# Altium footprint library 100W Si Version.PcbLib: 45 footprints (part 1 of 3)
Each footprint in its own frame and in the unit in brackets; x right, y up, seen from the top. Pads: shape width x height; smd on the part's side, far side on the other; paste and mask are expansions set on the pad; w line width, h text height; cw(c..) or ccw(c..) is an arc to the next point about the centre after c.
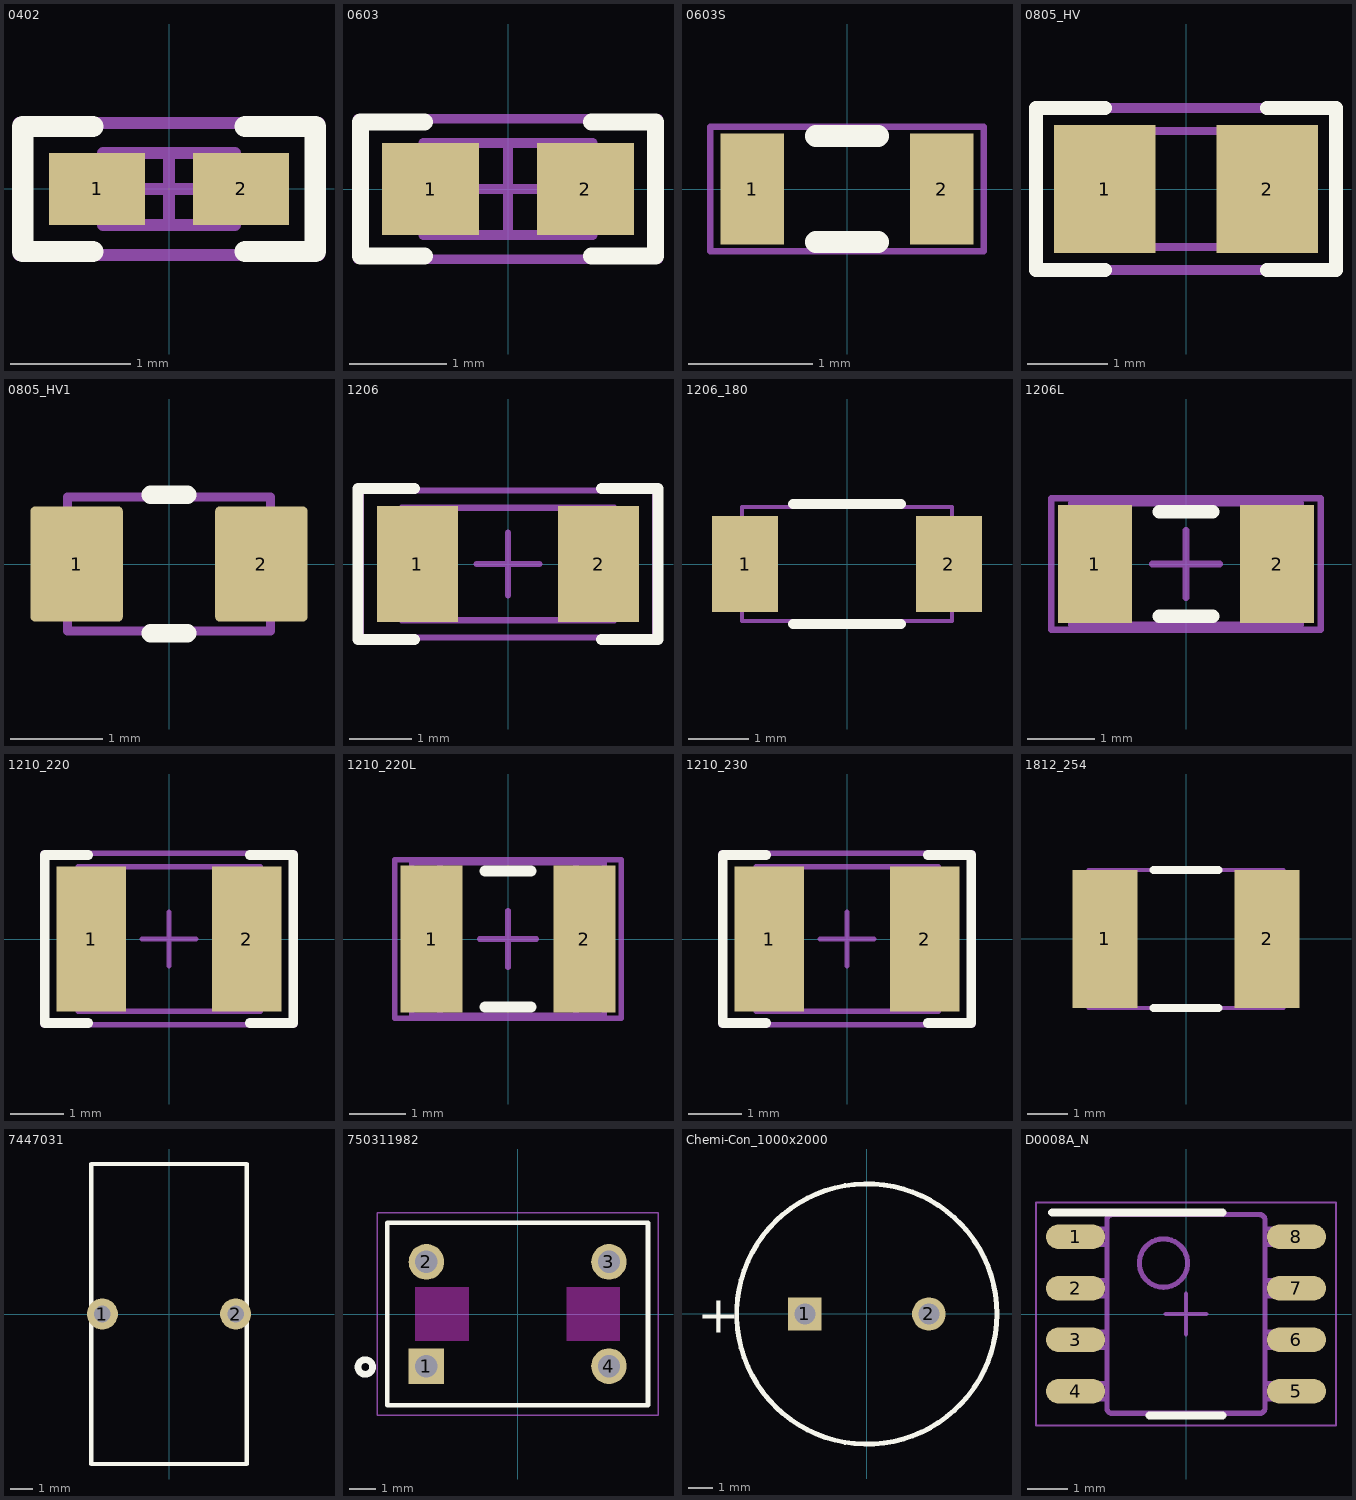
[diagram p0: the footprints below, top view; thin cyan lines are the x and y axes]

## 0402 [mm] "0402 from SM-752 data"
height 0.6
pads (2):
  rect 0.8x0.6 smd: 1(-0.6,0) 2(0.6,0)
Top Overlay:
  lines w0.178: -0.635,-0.521 -1.219,-0.521 -1.219,0.521 -0.635,0.521 ; 0.635,-0.521 1.219,-0.521 1.219,0.521 0.635,0.521
Mechanical 5:
  lines w0.1: -1.25,-0.55 1.25,-0.55 1.25,0.55 -1.25,0.55 -1.25,-0.55
  text ".Designator" at -1.117,-0.305 h0.76
Mechanical 13:
  lines w0.1: -0.35,-0.3 -0.35,0.3 ; 0.35,-0.3 0.35,0.3 ; -0.55,-0.3 -0.55,0.3 0.55,0.3 0.55,-0.3 -0.55,-0.3
Mechanical 15:
  lines w0.1: -0.3,0 0.3,0 ; 0,-0.3 0,0.3 ; -1.25,-0.55 -1.25,0.55 1.25,0.55 1.25,-0.55 -1.25,-0.55
3D body: height 0.6, standoff 0, extent -0.549,-0.299 -0.351,0.299
3D body: height 0.6, standoff 0, extent -0.349,-0.299 0.349,0.299
3D body: height 0.6, standoff 0, extent 0.351,-0.299 0.549,0.299

## 0603 [mm] "0603 from SM-752 data"
height 1
pads (2):
  rect 1x0.95 smd: 1(-0.8,0) 2(0.8,0)
Top Overlay:
  lines w0.178: -0.864,-0.691 -1.524,-0.691 -1.524,0.693 -0.864,0.693 ; 0.864,-0.691 1.524,-0.691 1.524,0.693 0.864,0.693
Mechanical 5:
  lines w0.1: -1.55,-0.725 1.55,-0.725 1.55,0.725 -1.55,0.725 -1.55,-0.725
  text ".Designator" at -1.397,-0.381 h0.76
Mechanical 13:
  lines w0.1: -0.55,-0.475 -0.55,0.475 ; 0.55,-0.475 0.55,0.475 ; -0.875,-0.475 -0.875,0.475 0.875,0.475 0.875,-0.475 -0.875,-0.475
Mechanical 15:
  lines w0.1: -0.475,0 0.475,0 ; 0,-0.475 0,0.475 ; -1.55,-0.725 -1.55,0.725 1.55,0.725 1.55,-0.725 -1.55,-0.725
3D body: height 1, standoff 0, extent 0.551,-0.474 0.874,0.474
3D body: height 1, standoff 0, extent -0.549,-0.474 0.549,0.474
3D body: height 1, standoff 0, extent -0.874,-0.474 -0.551,0.474

## 0603S [mil]
height 39.37
pads (2):
  rect 20x35 smd: 1(-30,0) 2(30,0)
Top Overlay:
  lines w7: -9.84,-16.73 9.84,-16.73 ; -9.84,16.73 9.84,16.73
Mechanical 5:
  lines w1.97: -43.31,-19.68 43.31,-19.68 43.31,19.68 -43.31,19.68 -43.31,-19.68
  text ".Designator" at -32.48,-8.86 h30
3D body: height 39.37, standoff 0, extent -34.43,-18.68 -21.67,18.68
3D body: height 39.37, standoff 0, extent -21.63,-18.68 21.63,18.68
3D body: height 39.37, standoff 0, extent 21.67,-18.68 34.43,18.68

## 0805_HV [mil] "0805 with 30mil clearance between pads"
height 57.09
pads (2):
  rect 50x63 smd: 1(-40,0) 2(40,0)
Top Overlay:
  lines w7: -40,-40 -74,-40 -74,0 -74,40 -40,40 ; 40,-40 74,-40 74,0 74,40 40,40
Mechanical 5:
  lines w5: -74,-40 -74,40 74,40 74,-40 -74,-40
  text ".Designator" at -64,-17 h35
Mechanical 13:
  lines w3.94: -25.59,-28.54 -25.59,28.54 ; 25.59,-28.54 25.59,28.54 ; -43.31,-28.54 -43.31,28.54 43.31,28.54 43.31,-28.54 -43.31,-28.54
3D body: height 57.09, standoff 0, extent 25.61,-28.52 43.29,28.52
3D body: height 57.09, standoff 0, extent -25.57,-28.52 25.57,28.52
3D body: height 57.09, standoff 0, extent -43.29,-28.52 -25.61,28.52

## 0805_HV1 [mm] "Custom footprint based on analyzing multiple manufacturer recommendations"
height 1.45
pads (2):
  rrect10% 1x1.25 smd: 1(-1,0) 2(1,0)
Top Overlay:
  lines w0.2: -0.2,-0.75 0.2,-0.75 ; -0.2,0.75 0.2,0.75
Mechanical 5:
  lines w0.1: -1.1,-0.725 -1.1,0.725 1.1,0.725 1.1,-0.725 -1.1,-0.725
  text ".Designator" at -0.925,-0.25 h0.51
3D body "0805_CapMax.stp": height 1.45, standoff 0, extent -1.1,-0.725 1.1,0.725

## 1206 [mm] "1206 from SM-752 data"
height 1.35
pads (2):
  rect 1.3x1.85 smd: 1(-1.45,0) 2(1.45,0)
Top Overlay:
  lines w0.178: -1.5,-1.21 -2.4,-1.21 -2.4,1.21 -1.5,1.21 ; 1.5,-1.21 2.4,-1.21 2.4,1.21 1.5,1.21
Mechanical 5:
  lines w0.1: -1.7,-0.9 1.7,-0.9 1.7,0.9 -1.7,0.9 -1.7,-0.9
  text ".Designator" at -1.475,-0.4 h0.81
Mechanical 13:
  lines w0.1: -1.2,-0.9 -1.2,0.9 ; 1.2,-0.9 1.2,0.9 ; -1.7,-0.9 1.7,-0.9 1.7,0.9 -1.7,0.9 -1.7,-0.9
Mechanical 15:
  lines w0.1: -0.5,0 0.5,0 ; 0,-0.5 0,0.5 ; -2.35,-1.175 2.35,-1.175 2.35,1.175 -2.35,1.175 -2.35,-1.175
3D body: height 1.35, standoff 0, extent -1.699,-0.899 -1.201,0.899
3D body: height 1.35, standoff 0, extent -1.199,-0.899 1.199,0.899
3D body: height 1.35, standoff 0, extent 1.201,-0.899 1.699,0.899

## 1206_180 [mm] "1206_180"
height 1.8
pads (2):
  rect 1.1x1.6 smd: 1(-1.7,0) 2(1.7,0)
Top Overlay:
  lines w0.17: -0.9,-1 0.9,-1 ; -0.9,1 0.9,1
Mechanical 5:
  lines w0.07: -1.75,-0.95 1.75,-0.95 1.75,0.95 -1.75,0.95 -1.75,-0.95
3D body: height 1.8, standoff 0, extent -1.749,-0.949 -1.301,0.949
3D body: height 1.8, standoff 0, extent -1.299,-0.949 1.299,0.949
3D body: height 1.8, standoff 0, extent 1.301,-0.949 1.749,0.949

## 1206L [mm] "1206 from SM-752 data"
height 1.35
pads (2):
  rect 1.1x1.75 smd: 1(-1.35,0) 2(1.35,0)
Top Overlay:
  lines w0.2: -0.4,-0.775 0.4,-0.775 ; -0.4,0.775 0.4,0.775
Mechanical 5:
  lines w0.1: -1.7,-0.9 1.7,-0.9 1.7,0.9 -1.7,0.9 -1.7,-0.9
  text ".Designator" at -1.475,-0.4 h0.81
Mechanical 13:
  lines w0.1: -1.2,-0.9 -1.2,0.9 ; 1.2,-0.9 1.2,0.9 ; -1.7,-0.9 -1.7,0.9 1.7,0.9 1.7,-0.9 -1.7,-0.9
Mechanical 15:
  lines w0.1: -0.5,0 0.5,0 ; 0,-0.5 0,0.5 ; -2,-0.975 2,-0.975 2,0.975 -2,0.975 -2,-0.975
3D body: height 1.35, standoff 0, extent 1.201,-0.899 1.699,0.899
3D body: height 1.35, standoff 0, extent -1.199,-0.899 1.199,0.899
3D body: height 1.35, standoff 0, extent -1.699,-0.899 -1.201,0.899

## 1210_220 [mm] "1210"
height 2.2
pads (2):
  rect 1.3x2.7 smd: 1(-1.45,0) 2(1.45,0)
Top Overlay:
  lines w0.178: -1.511,-1.568 -2.316,-1.568 -2.316,1.568 -1.511,1.568 ; 1.511,-1.568 2.316,-1.568 2.316,1.568 1.511,1.568
Mechanical 5:
  lines w0.1: -1.7,-1.35 -1.7,1.35 1.7,1.35 1.7,-1.35 -1.7,-1.35
  text ".Designator" at -1.4,-0.375 h0.76
Mechanical 13:
  lines w0.1: -1.2,-1.35 -1.2,1.35 ; 1.2,-1.35 1.2,1.35 ; -1.7,-1.35 1.7,-1.35 1.7,1.35 -1.7,1.35 -1.7,-1.35
Mechanical 15:
  lines w0.1: -0.5,0 0.5,0 ; 0,-0.5 0,0.5 ; -2.35,-1.6 2.35,-1.6 2.35,1.6 -2.35,1.6 -2.35,-1.6
3D body: height 2.2, standoff 0, extent 1.201,-1.349 1.699,1.349
3D body: height 2.2, standoff 0, extent -1.199,-1.349 1.199,1.349
3D body: height 2.2, standoff 0, extent -1.699,-1.349 -1.201,1.349

## 1210_220L [mm] "1210"
height 2.2
pads (2):
  rect 1.1x2.6 smd: 1(-1.35,0) 2(1.35,0)
Top Overlay:
  lines w0.2: -0.4,-1.2 0.4,-1.2 ; -0.4,1.2 0.4,1.2
Mechanical 5:
  lines w0.1: -1.7,-1.35 1.7,-1.35 1.7,1.35 -1.7,1.35 -1.7,-1.35
  text ".Designator" at -1.4,-0.375 h0.76
Mechanical 13:
  lines w0.1: -1.2,-1.35 -1.2,1.35 ; 1.2,-1.35 1.2,1.35 ; -1.7,-1.35 1.7,-1.35 1.7,1.35 -1.7,1.35 -1.7,-1.35
Mechanical 15:
  lines w0.1: -0.5,0 0.5,0 ; 0,-0.5 0,0.5 ; -2,-1.4 -2,1.4 2,1.4 2,-1.4 -2,-1.4
3D body: height 2.2, standoff 0, extent 1.201,-1.349 1.699,1.349
3D body: height 2.2, standoff 0, extent -1.199,-1.349 1.199,1.349
3D body: height 2.2, standoff 0, extent -1.699,-1.349 -1.201,1.349

## 1210_230 [mm] "1210"
height 2.3
pads (2):
  rect 1.3x2.7 smd: 1(-1.45,0) 2(1.45,0)
Top Overlay:
  lines w0.178: -1.511,-1.568 -2.316,-1.568 -2.316,1.568 -1.511,1.568 ; 1.511,-1.568 2.316,-1.568 2.316,1.568 1.511,1.568
Mechanical 5:
  lines w0.1: -1.7,-1.35 1.7,-1.35 1.7,1.35 -1.7,1.35 -1.7,-1.35
  text ".Designator" at -1.4,-0.375 h0.76
Mechanical 13:
  lines w0.1: -1.2,-1.35 -1.2,1.35 ; 1.2,-1.35 1.2,1.35 ; -1.7,-1.35 -1.7,1.35 1.7,1.35 1.7,-1.35 -1.7,-1.35
Mechanical 15:
  lines w0.1: -0.5,0 0.5,0 ; 0,-0.5 0,0.5 ; -2.35,-1.6 -2.35,1.6 2.35,1.6 2.35,-1.6 -2.35,-1.6
3D body: height 2.3, standoff 0, extent -1.699,-1.349 -1.201,1.349
3D body: height 2.3, standoff 0, extent -1.199,-1.349 1.199,1.349
3D body: height 2.3, standoff 0, extent 1.201,-1.349 1.699,1.349

## 1812_254 [mm] "SMD, 2-Leads, Body 4.8x3.4mm"
height 2.54
pads (2):
  rect 1.6x3.4 smd: 1(-2,0) 2(2,0)
Top Overlay:
  lines w0.2: -0.8,-1.7 0.8,-1.7 ; -0.8,1.7 0.8,1.7
Mechanical 5:
  lines w0.1: -1.9,-1.7 -1.9,1.7 ; 1.9,-1.7 1.9,1.7 ; -2.4,-1.7 2.4,-1.7 2.4,1.7 -2.4,1.7 -2.4,-1.7
  text ".Designator" at -1.875,-0.5 h1.02
3D body: height 2.54, standoff 0, extent -2.399,-1.699 -1.901,1.699
3D body: height 2.54, standoff 0, extent -1.899,-1.699 1.899,1.699
3D body: height 2.54, standoff 0, extent 1.901,-1.699 2.399,1.699

## 7447031 [mm] "Body 13.5x7mm, 2 leads"
height 13.5
pads (2):
  round 1.4 hole 0.75: 1(-3,0) 2(3,0)
Top Overlay:
  lines w0.2: -3.5,-6.75 -3.5,6.75 3.5,6.75 3.5,-6.75 -3.5,-6.75
3D body "7447031.stp": height 14.74, standoff -14.25, extent -4.01,-7.254 4.01,7.253

## 750311982 [mm] "4 LEAD,TH"
height 6.8
pads (4):
  rect 1.362x1.362 / inner round 1.362 / far side rect 1.362x1.362 hole 0.854: 1(-3.5,-2)
  round 1.362 hole 0.854: 2(-3.5,2) 3(3.5,2) 4(3.5,-2)
Top Layer keep-out:
  rectangle: -3.927,-1.027 -1.873,1.027
  rectangle: 1.873,-1.027 3.927,1.027
Top Overlay:
  circle w0.254: c-5.842,-2.032 r0.279
  lines w0.178: -5,-3.5 5,-3.5 5,3.5 -5,3.5 -5,-3.5
Bottom Overlay:
  lines w0.178: -5,-3.5 -5,-2.5 ; -5,-1.5 -5,-0.5 ; -5,0.5 -5,1.5 ; -5,2.5 -5,3.5 ; -4.572,-3.5 -3.572,-3.5 ; -4.572,3.5 -3.572,3.5 ; -2.572,-3.5 -1.572,-3.5 ; -2.572,3.5 -1.572,3.5 ; -0.572,-3.5 0.428,-3.5 ; -0.572,3.5 0.428,3.5 ; 1.428,-3.5 2.428,-3.5 ; 1.428,3.5 2.428,3.5 ; 3.428,-3.5 4.428,-3.5 ; 3.428,3.5 4.428,3.5 ; 5,-3.5 5,-2.5 ; 5,-1.5 5,-0.5 ; 5,0.5 5,1.5 ; 5,2.5 5,3.5
Mechanical 5:
  lines w0.127: -5,-3.5 -5,3.5 5,3.5 5,-3.5 -5,-3.5
  text ".Designator" at -0.61,1.27 h0.89
Mechanical 15:
  lines w0.05: -5.381,-3.881 5.381,-3.881 5.381,3.881 -5.381,3.881 -5.381,-3.881
Mechanical 17:
  text "LEAD LENGTH:3 +/- 0.5MM" at -10.795,1.651 h1.02
3D body: height 6.8, standoff 0, extent -5,-3.5 5,3.5

## Chemi-Con_1000x2000 [mm] "TH, 2-Leads, Body 10x20mm, Pin Spacing 5mm"
height 21.5
pads (2):
  rect 1.35x1.35 hole 0.85: 1(-2.5,0)
  round 1.35 hole 0.85: 2(2.5,0)
Top Overlay:
  circle w0.2: c0,0 r5.25
  text "+" at -6.85,-0.75 h1.5
Mechanical 5:
  lines w0.1: 5.25,-0.001 cw(c0,0) 5.25,0
  text "+" at -6.85,-0.75 h1.5
  text ".Designator" at -1.524,-0.508 h1.02
3D body: height 0, standoff -2.5, extent -2.797,-0.299 -2.2,0.3
3D body: height 0, standoff -2, extent 2.203,-0.299 2.8,0.3
3D body: height 21.5, standoff 0, extent -5.249,-5.25 4.55,5.25
3D body: height 21.5, standoff 0, extent 3.68,-2.626 5.25,2.622
3D body: height 21.5, standoff 0, extent -4.25,-4.25 4.249,4.249

## D0008A_N [mm] "SOIC, 8-Leads, Body 4.9x3.9mm, Pitch 1.27mm, IPC Medium Density"
height 1.75
pads (8):
  oval 1.45x0.6 smd: 1(-2.725,1.905) 2(-2.725,0.635) 3(-2.725,-0.635) 4(-2.725,-1.905) 5(2.725,-1.905) 6(2.725,-0.635) 7(2.725,0.635) 8(2.725,1.905)
Top Overlay:
  lines w0.2: -3.3,2.5 0.9,2.5 ; -0.9,-2.5 0.9,-2.5
Mechanical 5:
  lines w0.127: -2.375,-2.095 -2.375,-1.715 ; -2.375,-2.095 -2.589,-2.095 -3.002,-2.095 -3.002,-1.715 -2.589,-1.715 -2.375,-1.715 ; -2.375,-2.095 -1.995,-2.095 -1.952,-2.095 -1.952,-1.715 -1.995,-1.715 -2.375,-1.715 ; -2.375,-0.825 -2.375,-0.445 ; -2.375,-0.825 -2.589,-0.825 -3.002,-0.825 -3.002,-0.445 -2.589,-0.445 -2.375,-0.445 ; -2.375,-0.825 -1.995,-0.825 -1.952,-0.825 -1.952,-0.445 -1.995,-0.445 -2.375,-0.445 ; -2.375,0.445 -2.375,0.825 ; -2.375,0.445 -2.589,0.445 -3.002,0.445 -3.002,0.825 -2.589,0.825 -2.375,0.825 ; -2.375,0.445 -1.995,0.445 -1.952,0.445 -1.952,0.825 -1.995,0.825 -2.375,0.825 ; -2.375,1.715 -2.375,2.095 ; -2.375,1.715 -2.589,1.715 -3.002,1.715 -3.002,2.095 -2.589,2.095 -2.375,2.095 ; -2.375,1.715 -1.995,1.715 -1.952,1.715 -1.952,2.095 -1.995,2.095 -2.375,2.095 ; -0.332,-2.45 -0.182,-2.45 ; -0.332,-2.45 -0.182,-2.45 ; -0.332,-2.45 -1.825,-2.45 -1.826,-2.45 cw(c-1.825,-2.323) -1.952,-2.324 -1.952,-2.323 -1.952,2.323 -1.952,2.324 cw(c-1.825,2.323) -1.826,2.45 -1.825,2.45 -0.332,2.45 ; -0.332,2.45 -0.182,2.45 ; -0.332,2.45 -0.182,2.45 ; -0.182,-2.45 0.178,-2.45 ; -0.182,2.45 0.178,2.45 ; 0.178,-2.45 0.328,-2.45 ; 0.178,-2.45 0.328,-2.45 ; 0.178,2.45 0.328,2.45 ; 0.178,2.45 0.328,2.45 ; 0.328,-2.45 1.821,-2.45 1.822,-2.45 ccw(c1.821,-2.323) 1.948,-2.324 1.948,-2.323 1.948,2.323 1.948,2.324 ccw(c1.821,2.323) 1.822,2.45 1.821,2.45 0.328,2.45 ; 2.371,-2.095 2.371,-1.715 ; 2.371,-2.095 1.991,-2.095 1.948,-2.095 1.948,-1.715 1.991,-1.715 2.371,-1.715 ; 2.371,-2.095 2.585,-2.095 2.998,-2.095 2.998,-1.715 2.585,-1.715 2.371,-1.715 ; 2.371,-0.825 2.371,-0.445 ; 2.371,-0.825 1.991,-0.825 1.948,-0.825 1.948,-0.445 1.991,-0.445 2.371,-0.445 ; 2.371,-0.825 2.585,-0.825 2.998,-0.825 2.998,-0.445 2.585,-0.445 2.371,-0.445 ; 2.371,0.445 2.371,0.825 ; 2.371,0.445 1.991,0.445 1.948,0.445 1.948,0.825 1.991,0.825 2.371,0.825 ; 2.371,0.445 2.585,0.445 2.998,0.445 2.998,0.825 2.585,0.825 2.371,0.825 ; 2.371,1.715 2.371,2.095 ; 2.371,1.715 1.991,1.715 1.948,1.715 1.948,2.095 1.991,2.095 2.371,2.095 ; 2.371,1.715 2.585,1.715 2.998,1.715 2.998,2.095 2.585,2.095 2.371,2.095 ; -0.555,0.659 ccw(c-0.555,1.256) -0.555,1.853 ccw(c-0.555,1.256) -0.555,0.659
  text ".Designator" at -1.625,-0.625 h0.76
Mechanical 15:
  lines w0.05: -3.7,-2.75 -3.7,2.75 3.7,2.75 3.7,-2.75 -3.7,-2.75
  lines w0.1: -0.5,0 0.5,0 ; 0,-0.5 0,0.5
3D body "D0008A.stp": height 1.63, standoff 0, extent -3,-2.45 3,2.45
